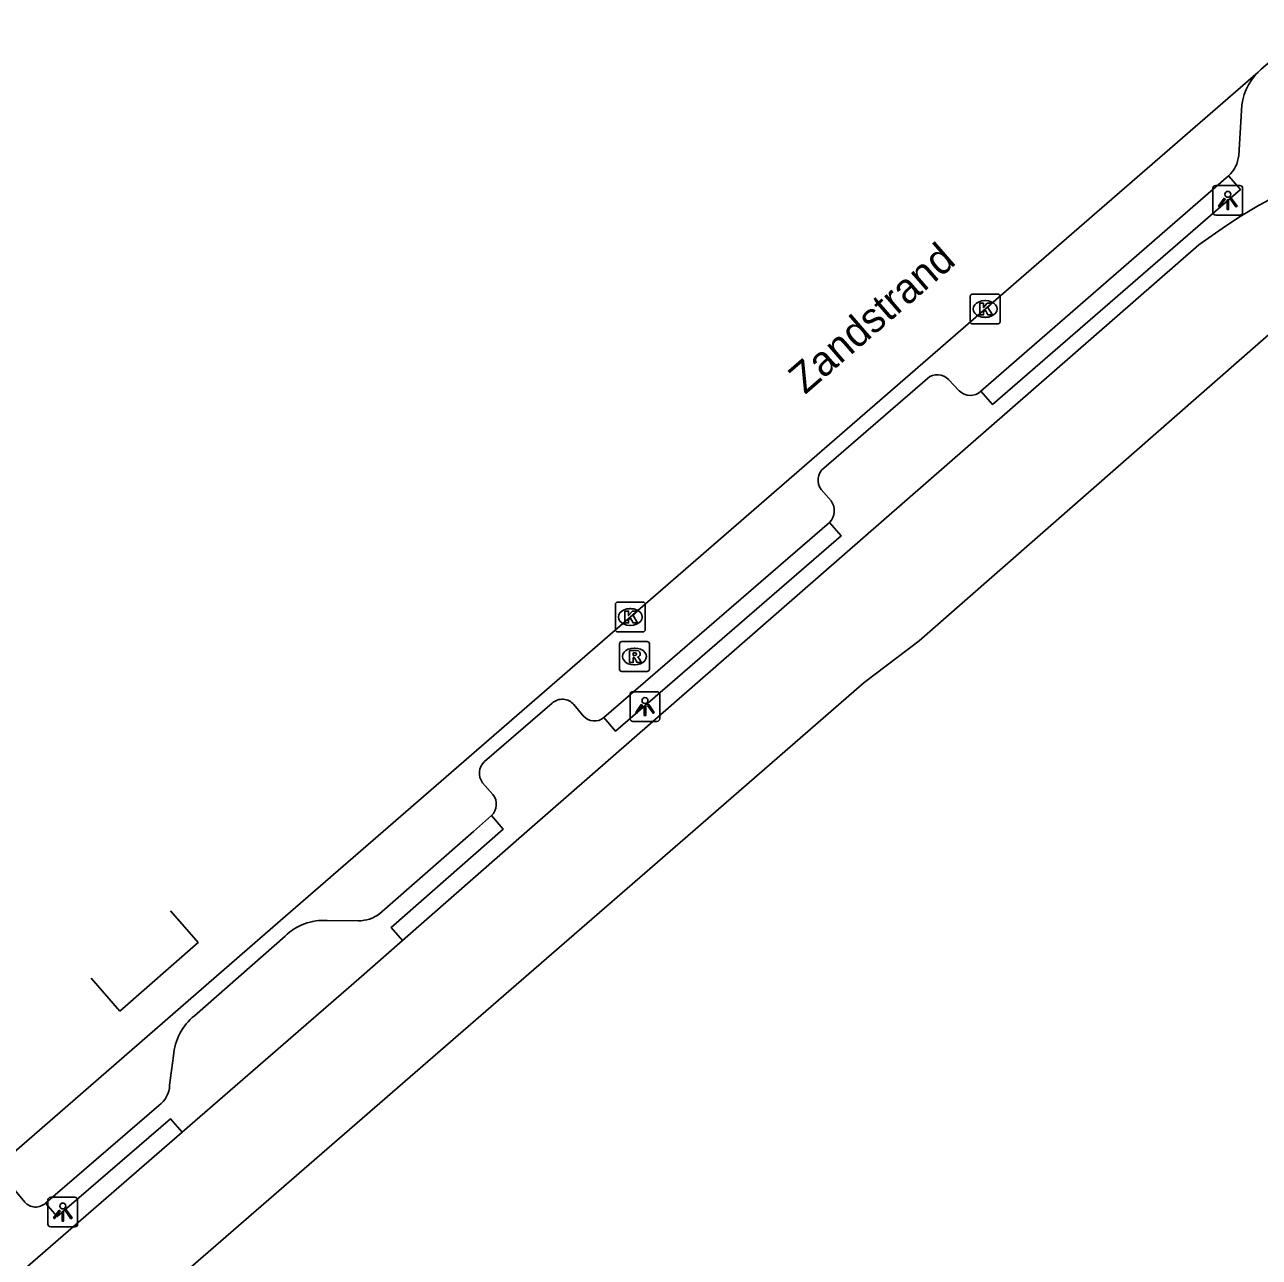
# Model space of a CAD drawing. Extents: x 155640 to 156810, y 382822 to 384046.
# Drawn here: x 156450.98 to 156492.42, y 383985.71 to 384027.08 of the extents above; entities that cross this region are included whole.
import ezdxf

# ---------------------------------------------------------------- set-up
doc = ezdxf.new("R2010")
doc.units = 0
for name, color, linetype in [('IMGEO_Berm_open', 7, 'Continuous'), ('IMGEO_Fietspad_gesloten', 7, 'Continuous'), ('IMGEO_Kolk', 7, 'Continuous'), ('IMGEO_Lichtpunt', 7, 'Continuous'), ('IMGEO_Openbare_ruimte_label', 7, 'Continuous'), ('IMGEO_Parkeervlak_open', 7, 'Continuous'), ('IMGEO_Rijbaan_lokaal_gesloten', 7, 'Continuous'), ('IMGEO_Rijbaan_lokaal_open', 7, 'Continuous'), ('IMGEO_Rioolput', 7, 'Continuous')]:
    doc.layers.add(name, color=color, linetype=linetype)

msp = doc.modelspace()

# ---------------------------------------------------------------- linework, layer by layer
at = {"layer": 'IMGEO_Berm_open'}
for points in [[(156491.388, 384022.009), (156491.782, 384021.556), (156483.465, 384014.33), (156483.071, 384014.783)], [(156477.987, 384010.378), (156478.38, 384009.924), (156470.812, 384003.37), (156470.419, 384003.824)], [(156466.647, 384000.534), (156467.043, 384000.083), (156463.282, 383996.784), (156463.665, 383996.347)], [(156456.26, 383989.906), (156455.876, 383990.352), (156452.071, 383987.075), (156451.679, 383987.53)]]:
    msp.add_lwpolyline(points, dxfattribs=at)
at = {"layer": 'IMGEO_Fietspad_gesloten'}
for points in [[(156463.665, 383996.347), (156467.831, 384000), (156490.392, 384019.695), (156491.286, 384020.324)], [(156493.456, 384017.313), (156481.006, 384006.405), (156479.158, 384005), (156473.402, 384000), (156464.513, 383992.278), (156412.558, 383947.186)], [(156456.26, 383989.906), (156462.195, 383995.059), (156463.665, 383996.347)], [(156414.861, 383953.961), (156456.26, 383989.906)]]:
    msp.add_lwpolyline(points, dxfattribs=at)
msp.add_arc((156501.522, 384005.13), 18.32, 110.8969, 123.9661, dxfattribs=at)
at = {"layer": 'IMGEO_Kolk'}
for p, q in [((156482.715, 384017.115), (156482.715, 384017.967)), ((156482.79, 384018.041), (156483.642, 384018.041)), ((156483.716, 384017.967), (156483.716, 384017.115)), ((156483.203, 384017.821), (156483.228, 384017.821)), ((156483.226, 384017.261), (156483.201, 384017.261)), ((156483.642, 384017.041), (156482.79, 384017.041)), ((156470.805, 384006.776), (156470.805, 384007.628)), ((156470.88, 384007.702), (156471.732, 384007.702)), ((156471.806, 384007.628), (156471.806, 384006.776)), ((156471.293, 384007.482), (156471.318, 384007.482)), ((156471.316, 384006.922), (156471.291, 384006.922)), ((156471.732, 384006.702), (156470.88, 384006.702))]:
    msp.add_line(p, q, dxfattribs=at)
for points in [[(156482.715, 384017.115), (156482.715, 384017.967)], [(156482.79, 384018.041), (156483.642, 384018.041)], [(156483.716, 384017.967), (156483.716, 384017.115)], [(156483.036, 384017.741), (156483.159, 384017.741), (156483.159, 384017.59), (156483.289, 384017.741), (156483.453, 384017.741), (156483.307, 384017.59), (156483.46, 384017.341), (156483.308, 384017.341), (156483.223, 384017.505), (156483.159, 384017.438), (156483.159, 384017.341), (156483.036, 384017.341), (156483.036, 384017.741)], [(156483.642, 384017.041), (156482.79, 384017.041)], [(156470.805, 384006.776), (156470.805, 384007.628)], [(156470.88, 384007.702), (156471.732, 384007.702)], [(156471.806, 384007.628), (156471.806, 384006.776)], [(156471.126, 384007.402), (156471.249, 384007.402), (156471.249, 384007.251), (156471.379, 384007.402), (156471.543, 384007.402), (156471.397, 384007.251), (156471.55, 384007.002), (156471.398, 384007.002), (156471.313, 384007.166), (156471.249, 384007.099), (156471.249, 384007.002), (156471.126, 384007.002), (156471.126, 384007.402)], [(156471.732, 384006.702), (156470.88, 384006.702)]]:
    msp.add_lwpolyline(points, dxfattribs=at)
for centre, start, end in [((156482.792, 384017.965), 91.552, 178.448), ((156482.792, 384017.965), 91.552, 178.448), ((156483.64, 384017.965), 1.552, 88.448), ((156483.64, 384017.965), 1.552, 88.448), ((156482.792, 384017.117), 181.552, 268.448), ((156482.792, 384017.117), 181.552, 268.448), ((156483.64, 384017.117), 271.552, 358.448), ((156483.64, 384017.117), 271.552, 358.448), ((156470.882, 384007.626), 91.552, 178.448), ((156470.882, 384007.626), 91.552, 178.448), ((156471.73, 384007.626), 1.552, 88.448), ((156471.73, 384007.626), 1.552, 88.448), ((156470.882, 384006.778), 181.552, 268.448), ((156470.882, 384006.778), 181.552, 268.448), ((156471.73, 384006.778), 271.552, 358.448), ((156471.73, 384006.778), 271.552, 358.448)]:
    msp.add_arc(centre, 0.0765, start, end, dxfattribs=at)
for centre, major_axis, ratio, start_param, end_param in [((156483.202, 384017.541), (-0.387, 0.002), 0.722429, 4.712389, 7.853982), ((156483.227, 384017.541), (-0.39, 0.002), 0.717154, 1.570796, 4.712389), ((156471.292, 384007.202), (-0.387, 0.002), 0.722429, 4.712389, 7.853982), ((156471.317, 384007.202), (-0.39, 0.002), 0.717154, 1.570796, 4.712389)]:
    msp.add_ellipse(centre, major_axis=major_axis, ratio=ratio, start_param=start_param, end_param=end_param, dxfattribs=at)
at = {"layer": 'IMGEO_Lichtpunt'}
for p, q in [((156491.764, 384021.687), (156490.956, 384021.687)), ((156491.764, 384021.687), (156490.956, 384021.687)), ((156490.862, 384021.592), (156490.862, 384020.785)), ((156490.862, 384021.592), (156490.862, 384020.785)), ((156491.858, 384020.785), (156491.858, 384021.592)), ((156491.858, 384020.785), (156491.858, 384021.592)), ((156490.956, 384020.691), (156491.764, 384020.691)), ((156490.956, 384020.691), (156491.764, 384020.691)), ((156472.201, 384004.693), (156471.393, 384004.693)), ((156472.201, 384004.693), (156471.393, 384004.693)), ((156471.299, 384004.598), (156471.299, 384003.791)), ((156471.299, 384004.598), (156471.299, 384003.791)), ((156472.295, 384003.791), (156472.295, 384004.598)), ((156472.295, 384003.791), (156472.295, 384004.598)), ((156471.393, 384003.697), (156472.201, 384003.697)), ((156471.393, 384003.697), (156472.201, 384003.697)), ((156452.661, 383987.728), (156451.853, 383987.728)), ((156452.661, 383987.728), (156451.853, 383987.728)), ((156451.759, 383987.633), (156451.759, 383986.826)), ((156451.759, 383987.633), (156451.759, 383986.826)), ((156452.755, 383986.826), (156452.755, 383987.633)), ((156452.755, 383986.826), (156452.755, 383987.633)), ((156451.853, 383986.732), (156452.661, 383986.732)), ((156451.853, 383986.732), (156452.661, 383986.732))]:
    msp.add_line(p, q, dxfattribs=at)
for points in [[(156491.236, 384021.256), (156491.275, 384021.228), (156491.087, 384020.966), (156491.049, 384020.993), (156491.236, 384021.256)], [(156491.448, 384021.228), (156491.486, 384021.255), (156491.673, 384020.993), (156491.634, 384020.965), (156491.448, 384021.228)], [(156491.338, 384021.208), (156491.385, 384021.208), (156491.385, 384020.886), (156491.338, 384020.886), (156491.338, 384021.208)], [(156471.673, 384004.262), (156471.712, 384004.234), (156471.524, 384003.972), (156471.486, 384003.999), (156471.673, 384004.262)], [(156471.885, 384004.234), (156471.923, 384004.261), (156472.11, 384003.999), (156472.071, 384003.971), (156471.885, 384004.234)], [(156471.775, 384004.214), (156471.822, 384004.214), (156471.822, 384003.892), (156471.775, 384003.892), (156471.775, 384004.214)], [(156452.133, 383987.297), (156452.172, 383987.269), (156451.984, 383987.007), (156451.946, 383987.034), (156452.133, 383987.297)], [(156452.345, 383987.269), (156452.383, 383987.296), (156452.57, 383987.034), (156452.531, 383987.006), (156452.345, 383987.269)], [(156452.235, 383987.249), (156452.282, 383987.249), (156452.282, 383986.927), (156452.235, 383986.927), (156452.235, 383987.249)]]:
    msp.add_lwpolyline(points, dxfattribs=at)
for centre in [(156491.361, 384021.39), (156471.798, 384004.396), (156452.258, 383987.431)]:
    msp.add_circle(centre, 0.0994, dxfattribs=at)
for centre, start, end in [((156490.956, 384021.592), 90, 180), ((156490.956, 384021.592), 90, 180), ((156491.764, 384021.592), 0, 90), ((156491.764, 384021.592), 0, 90), ((156490.956, 384020.785), 180, 270), ((156490.956, 384020.785), 180, 270), ((156491.764, 384020.785), 270, 0), ((156491.764, 384020.785), 270, 360), ((156471.393, 384004.598), 90, 180), ((156471.393, 384004.598), 90, 180), ((156472.201, 384004.598), 0, 90), ((156472.201, 384004.598), 0, 90), ((156471.393, 384003.791), 180, 270), ((156471.393, 384003.791), 180, 270), ((156472.201, 384003.791), 270, 0), ((156472.201, 384003.791), 270, 360), ((156451.853, 383987.633), 90, 180), ((156451.853, 383987.633), 90, 180), ((156452.661, 383987.633), 0, 90), ((156452.661, 383987.633), 0, 90), ((156451.853, 383986.826), 180, 270), ((156451.853, 383986.826), 180, 270), ((156452.661, 383986.826), 270, 0), ((156452.661, 383986.826), 270, 360)]:
    msp.add_arc(centre, 0.0946, start, end, dxfattribs=at)
at = {"layer": 'IMGEO_Parkeervlak_open'}
for points in [[(156491.821, 384024.208), (156491.728, 384022.69)], [(156491.388, 384022.009), (156483.071, 384014.783)], [(156481.281, 384015.213), (156477.797, 384012.199)], [(156482.349, 384014.793), (156481.987, 384015.174)], [(156477.708, 384011.485), (156478.042, 384011.102)], [(156477.987, 384010.378), (156470.419, 384003.824)], [(156468.682, 384004.308), (156466.413, 384002.347)], [(156469.725, 384003.884), (156469.412, 384004.267)], [(156466.349, 384001.636), (156466.697, 384001.245)], [(156466.647, 384000.534), (156466.038, 384000), (156462.886, 383997.235)], [(156462.183, 383997.005), (156461.136, 383997.016)], [(156459.717, 383996.489), (156456.681, 383993.818)], [(156455.969, 383992.475), (156455.844, 383991.482)], [(156455.484, 383990.807), (156451.679, 383987.53)], [(156450.979, 383987.562), (156450.66, 383987.952)]]:
    msp.add_lwpolyline(points, dxfattribs=at)
for centre, radius, start, end in [((156493.718, 384024.146), 1.898, 134.7839, 178.1212), ((156490.657, 384022.799), 1.076, 312.7583, 354.179), ((156481.614, 384014.824), 0.512, 43.1486, 130.5277), ((156482.715, 384015.161), 0.519, 225.1666, 313.2464), ((156478.125, 384011.796), 0.52, 129.0945, 216.695), ((156477.607, 384010.771), 0.547, 314.068, 37.2435), ((156469.027, 384003.934), 0.509, 40.8959, 132.6749), ((156470.103, 384004.207), 0.497, 220.5545, 309.563), ((156466.762, 384001.957), 0.523, 131.8688, 217.8441), ((156466.279, 384000.917), 0.531, 313.8294, 38.1254), ((156462.177, 383998.213), 1.208, 270.2827, 305.9503), ((156461.024, 383995.144), 1.876, 86.5779, 134.1709), ((156457.878, 383992.323), 1.915, 128.6924, 175.4465), ((156454.965, 383991.517), 0.88, 306.1655, 357.6895), ((156451.344, 383987.879), 0.484, 220.9836, 313.7816)]:
    msp.add_arc(centre, radius, start, end, dxfattribs=at)
at = {"layer": 'IMGEO_Rijbaan_lokaal_gesloten'}
for points in [[(156492.381, 384025.493), (156492.482, 384025.587), (156494.22, 384027.084)], [(156410.443, 383954.286), (156459.568, 383997.014), (156463.008, 384000), (156492.381, 384025.493)]]:
    msp.add_lwpolyline(points, dxfattribs=at)
at = {"layer": 'IMGEO_Rijbaan_lokaal_open'}
for points in [[(156455.868, 383997.337), (156456.798, 383996.277), (156454.172, 383993.966)], [(156454.172, 383993.966), (156453.209, 383995.074)]]:
    msp.add_lwpolyline(points, dxfattribs=at)
at = {"layer": 'IMGEO_Rioolput'}
for p, q in [((156471.019, 384006.376), (156471.871, 384006.376)), ((156470.944, 384005.45), (156470.944, 384006.302)), ((156471.432, 384006.156), (156471.457, 384006.156)), ((156471.945, 384006.302), (156471.945, 384005.45)), ((156471.455, 384005.596), (156471.43, 384005.596)), ((156471.871, 384005.376), (156471.019, 384005.376))]:
    msp.add_line(p, q, dxfattribs=at)
for points in [[(156471.019, 384006.376), (156471.871, 384006.376)], [(156470.944, 384005.45), (156470.944, 384006.302)], [(156471.533, 384006.074), (156471.281, 384006.076), (156471.281, 384005.676)], [(156471.459, 384005.995), (156471.405, 384005.995), (156471.405, 384005.914)], [(156471.405, 384005.914), (156471.457, 384005.914)], [(156471.945, 384006.302), (156471.945, 384005.45)], [(156471.281, 384005.676), (156471.405, 384005.676), (156471.405, 384005.838), (156471.416, 384005.838)], [(156471.463, 384005.809), (156471.534, 384005.676), (156471.674, 384005.676), (156471.609, 384005.802)], [(156471.871, 384005.376), (156471.019, 384005.376)]]:
    msp.add_lwpolyline(points, dxfattribs=at)
for centre, radius, start, end in [((156471.021, 384006.3), 0.0765, 91.552, 178.448), ((156471.021, 384006.3), 0.0765, 91.552, 178.448), ((156471.869, 384006.3), 0.0765, 1.552, 88.448), ((156471.869, 384006.3), 0.0765, 1.552, 88.448), ((156471.441, 384006.103), 0.19, 274.7715, 282.9687), ((156471.465, 384005.899), 0.0964, 77.0061, 93.1865), ((156471.479, 384005.956), 0.0378, 276.6634, 79.6772), ((156471.532, 384005.964), 0.109, 350.3612, 89.416), ((156471.53, 384005.964), 0.112, 277.5842, 350.9817), ((156471.415, 384005.785), 0.0533, 26.0293, 88.6989), ((156471.514, 384005.749), 0.108, 29.5134, 73.7905), ((156471.021, 384005.452), 0.0765, 181.552, 268.448), ((156471.021, 384005.452), 0.0765, 181.552, 268.448), ((156471.869, 384005.452), 0.0765, 271.552, 358.448), ((156471.869, 384005.452), 0.0765, 271.552, 358.448)]:
    msp.add_arc(centre, radius, start, end, dxfattribs=at)
for centre, major_axis, ratio, start_param, end_param in [((156471.431, 384005.876), (-0.387, 0.002), 0.722429, 4.712389, 7.853982), ((156471.456, 384005.876), (-0.39, 0.002), 0.717154, 1.570796, 4.712389)]:
    msp.add_ellipse(centre, major_axis=major_axis, ratio=ratio, start_param=start_param, end_param=end_param, dxfattribs=at)

# ---------------------------------------------------------------- texts
at = {"layer": 'IMGEO_Openbare_ruimte_label'}
msp.add_text('Zandstrand', height=1, rotation=40.9057, dxfattribs=at).set_placement((156477.17, 384014.65))

doc.saveas('drawing.dxf')
